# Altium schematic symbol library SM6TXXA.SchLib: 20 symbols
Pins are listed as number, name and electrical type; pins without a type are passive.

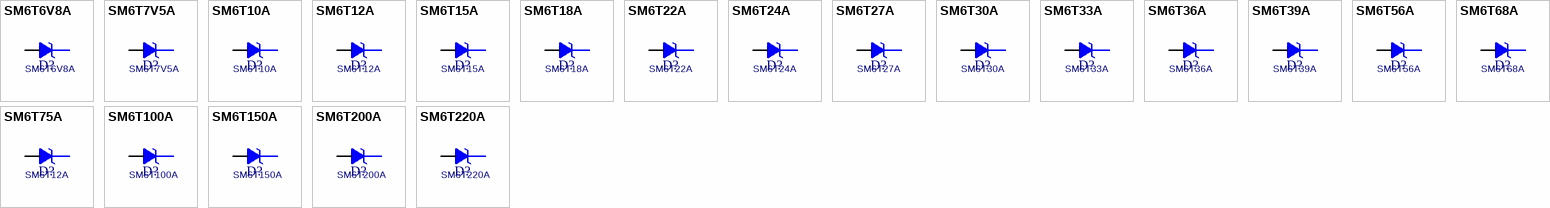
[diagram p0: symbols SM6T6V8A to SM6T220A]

## SM6T6V8A
designator D?
footprint ST_SMB
pins: 1 K, 2 A

## SM6T7V5A
designator D?
footprint ST_SMB
pins: 1 K, 2 A

## SM6T10A
designator D?
footprint ST_SMB
pins: 1 K, 2 A

## SM6T12A
designator D?
footprint ST_SMB
pins: 1 K, 2 A

## SM6T15A
designator D?
footprint ST_SMB
pins: 1 K, 2 A

## SM6T18A
designator D?
footprint ST_SMB
pins: 1 K, 2 A

## SM6T22A
designator D?
footprint ST_SMB
pins: 1 K, 2 A

## SM6T24A
designator D?
footprint ST_SMB
pins: 1 K, 2 A

## SM6T27A
designator D?
footprint ST_SMB
pins: 1 K, 2 A

## SM6T30A
designator D?
footprint ST_SMB
pins: 1 K, 2 A

## SM6T33A
designator D?
footprint ST_SMB
pins: 1 K, 2 A

## SM6T36A
designator D?
footprint ST_SMB
pins: 1 K, 2 A

## SM6T39A
designator D?
footprint ST_SMB
pins: 1 K, 2 A

## SM6T56A
designator D?
footprint ST_SMB
pins: 1 K, 2 A

## SM6T68A
designator D?
footprint ST_SMB
pins: 1 K, 2 A

## SM6T75A
designator D?, comment SM6T12A
footprint ST_SMB
pins: 1 K, 2 A

## SM6T100A
designator D?
footprint ST_SMB
pins: 1 K, 2 A

## SM6T150A
designator D?
footprint ST_SMB
pins: 1 K, 2 A

## SM6T200A
designator D?
footprint ST_SMB
pins: 1 K, 2 A

## SM6T220A
designator D?
footprint ST_SMB
pins: 1 K, 2 A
